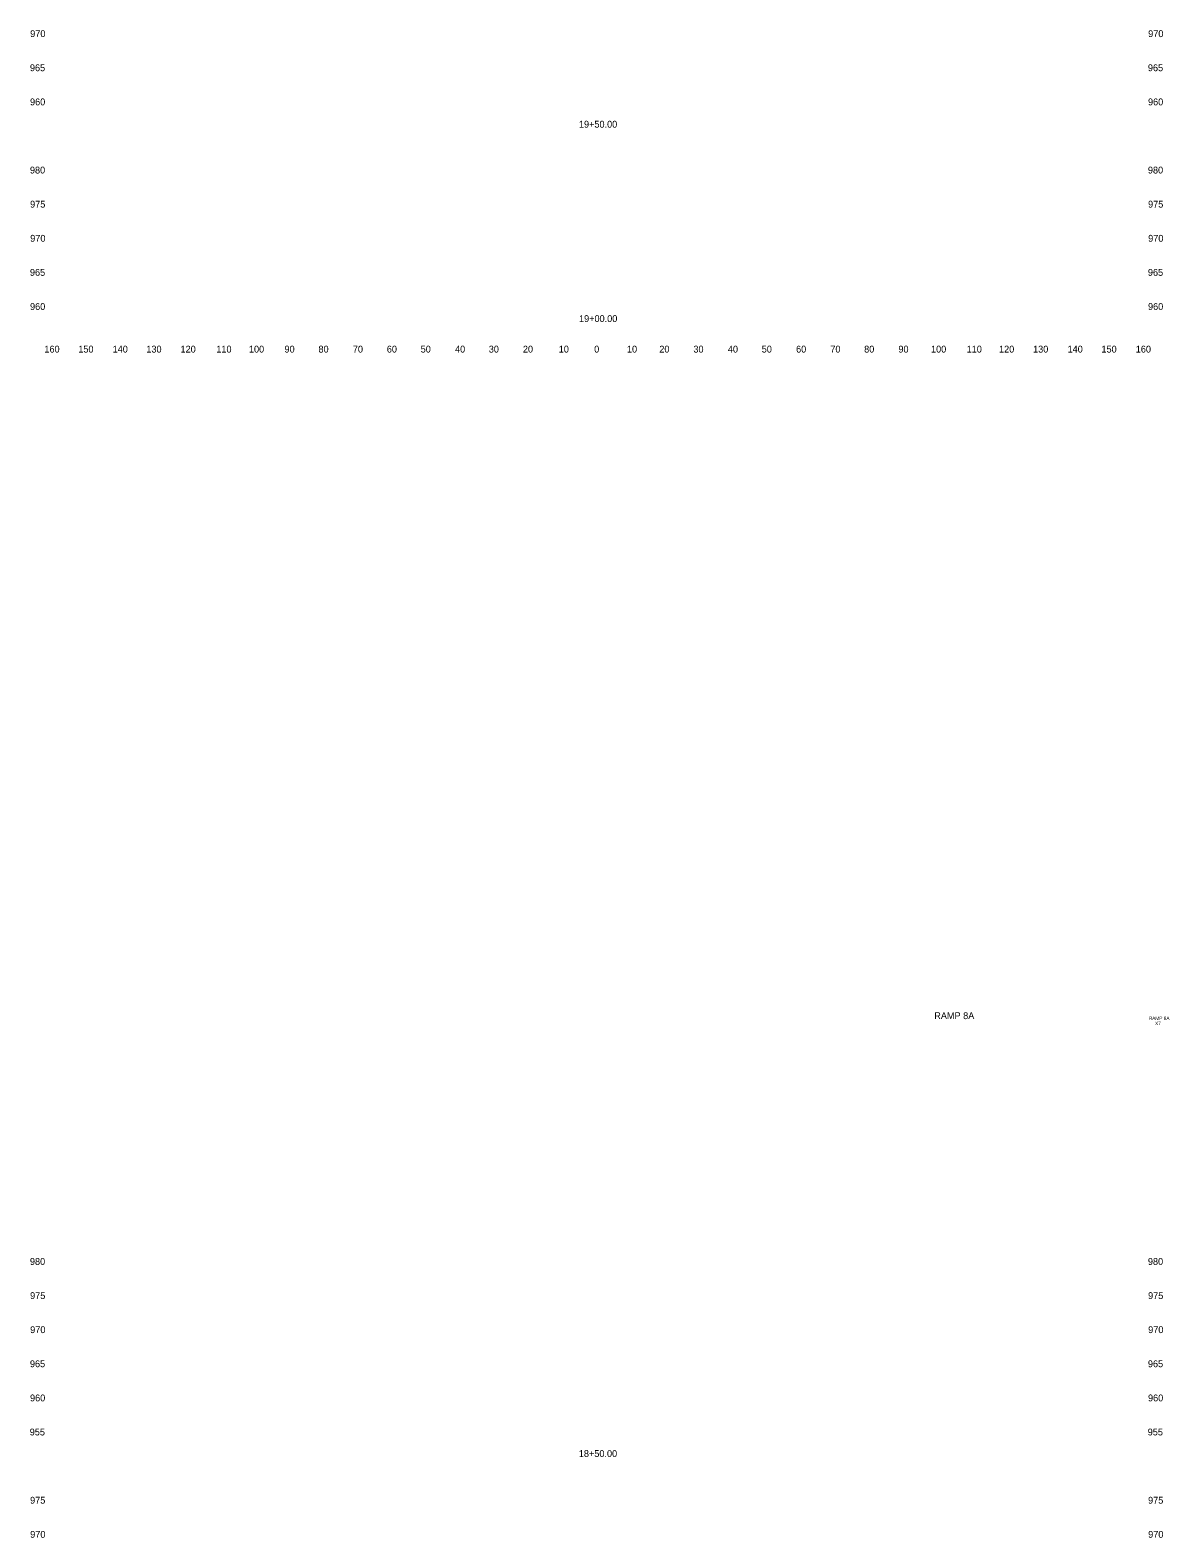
# Model space of a CAD drawing. Extents: x 4994 to 5328, y 4997 to 8804.
# Drawn here: x 4993.9 to 5327.8, y 7450 to 7892 of the extents above; entities that cross this region are included whole.
import ezdxf

# ---------------------------------------------------------------- set-up
doc = ezdxf.new("R2010")
doc.units = 0
for name, color, linetype in [('RD_SHT_ID', 7, 'Continuous'), ('RD_XS_TX_Offset', 7, 'Continuous'), ('RD_XS_TX_Station', 7, 'Continuous')]:
    doc.layers.add(name, color=color, linetype=linetype)

msp = doc.modelspace()

# ---------------------------------------------------------------- texts
at = {"layer": 'RD_SHT_ID'}
for s, height, p in [('RAMP 8A', 2, (5259.02, 7602.06)), ('RAMP 8A', 1, (5321.93, 7601.8)), ('X7', 1, (5323.74, 7600.3))]:
    msp.add_text(s, height=height, dxfattribs=at).set_placement(p)
at = {"layer": 'RD_XS_TX_Offset'}
for s, p in [('970', (4993.94, 7890)), ('970', (5321.74, 7890)), ('965', (4993.86, 7880)), ('965', (5321.66, 7880)), ('960', (4993.89, 7870)), ('960', (5321.69, 7870)), ('980', (4993.86, 7850)), ('980', (5321.66, 7850)), ('975', (4993.91, 7840)), ('975', (5321.71, 7840)), ('970', (4993.94, 7830)), ('970', (5321.74, 7830)), ('965', (4993.86, 7820)), ('965', (5321.66, 7820)), ('960', (4993.89, 7810)), ('960', (5321.69, 7810)), ('160', (4998.1, 7797.5)), ('150', (5008.04, 7797.5)), ('140', (5018.1, 7797.5)), ('130', (5027.99, 7797.5)), ('120', (5038.01, 7797.5)), ('110', (5048.51, 7797.5)), ('100', (5058.07, 7797.5)), ('90', (5068.5, 7797.5)), ('80', (5078.46, 7797.5)), ('70', (5088.54, 7797.5)), ('60', (5098.5, 7797.5)), ('50', (5108.43, 7797.5)), ('40', (5118.5, 7797.5)), ('30', (5128.39, 7797.5)), ('20', (5138.4, 7797.5)), ('10', (5148.91, 7797.5)), ('0', (5159.3, 7797.5)), ('0', (5159.3, 7797.5)), ('10', (5168.91, 7797.5)), ('20', (5178.4, 7797.5)), ('30', (5188.39, 7797.5)), ('40', (5198.5, 7797.5)), ('50', (5208.43, 7797.5)), ('60', (5218.5, 7797.5)), ('70', (5228.54, 7797.5)), ('80', (5238.46, 7797.5)), ('90', (5248.5, 7797.5)), ('100', (5258.07, 7797.5)), ('110', (5268.51, 7797.5)), ('120', (5278.01, 7797.5)), ('130', (5287.99, 7797.5)), ('140', (5298.1, 7797.5)), ('150', (5308.04, 7797.5)), ('160', (5318.1, 7797.5)), ('980', (4993.86, 7530)), ('980', (5321.66, 7530)), ('975', (4993.91, 7520)), ('975', (5321.71, 7520)), ('970', (4993.94, 7510)), ('970', (5321.74, 7510)), ('965', (4993.86, 7500)), ('965', (5321.66, 7500)), ('960', (4993.89, 7490)), ('960', (5321.69, 7490)), ('955', (4993.8, 7480)), ('955', (5321.6, 7480)), ('975', (4993.91, 7460)), ('975', (5321.71, 7460)), ('970', (4993.94, 7450)), ('970', (5321.74, 7450))]:
    msp.add_text(s, height=2, dxfattribs=at).set_placement(p)
at = {"layer": 'RD_XS_TX_Station'}
for s, p in [('19+50.00', (5154.83, 7863.45)), ('19+00.00', (5154.86, 7806.46)), ('18+50.00', (5154.8, 7473.69))]:
    msp.add_text(s, height=2, dxfattribs=at).set_placement(p)

doc.saveas('drawing.dxf')
